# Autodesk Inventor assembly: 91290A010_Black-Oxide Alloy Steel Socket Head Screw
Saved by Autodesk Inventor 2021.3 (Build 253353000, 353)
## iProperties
Created: 2022-04
Part Number: 91290A010_Black-Oxide Alloy Steel Socket Head Screw
Document SubType Name: Assembly
Designer: Administrator
Title: 91290A010_Black-Oxide Alloy Steel Socket Head Screw v2
Author: Administrator
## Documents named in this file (2)
- c:\worker\convert-fusion-r02\tmp\job-1\57\output\files\f9e42cba-e390-44b0-9630-f24d5638462a\91290A010_Black-Oxide Alloy Steel Socket Head Screw v2_1.iam
- c:\worker\convert-fusion-r02\tmp\job-1\57\output\files\f9e42cba-e390-44b0-9630-f24d5638462a\Component1_1.ipt
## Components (1 placed, 1 different names)
1. Component1:1
